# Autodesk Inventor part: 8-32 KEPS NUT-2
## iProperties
Created: 2007-09
Part Number: 8-32 KEPS NUT-2
Document SubType Name: Modeling
Material: Stainless Steel
Density: 8.08 g/cm^3
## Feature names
1. Base1
